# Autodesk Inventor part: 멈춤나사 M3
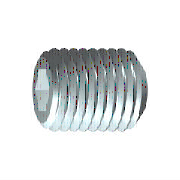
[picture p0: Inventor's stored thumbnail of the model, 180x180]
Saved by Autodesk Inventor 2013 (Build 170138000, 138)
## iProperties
IsCustomPart: 1
Created: 2012-02
Part Number: 멈춤나사 M3
Material: 강철, 연강
Description: 6각 소켓 머리 없는 멈춤 나사
Document SubType Name: Modeling
Standard: KS B 1028
Designer: mduedu
Standards Organization: KS
Language: ko-KR
Size Designation: 납작점M3x8
Categories: <MemberInstance><Categories><Category DisplayName="조임쇠" InternalName="e4da775c-781d-43d5-af7c-5136215cf5a6" Mnemonic="FSTN"><Category DisplayName="볼트" InternalN
Density: 1 g/cm^3
Author: mduedu
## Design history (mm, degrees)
sketch "스케치1"
  geometry: L1 (0, 0)-(5.5, 0); L2 (8, 0.866)-(8, 1.5); L3 (8, 1.5)-(0, 1.5); L4 (8, 0.866)-(6, 0.866); L5 (6, 0.866)-(5.5, 0); L6 (0, -0.3)-(0, 1.8) reference; L7 (0, 1.5)-(0, 0)
  constraints: 13 end point, 3 parallel, 1 collinear, 1 perpendicular, 1 point on line
  dimensions: "d0" = 2 distance of L2.start L4.end (= INTI); "d1" = 60 deg angle of L5 L1; "d2" = 3 diameter of L3 L1 (= NND); "d3" = 1.73205 diameter of L4 L1 (= 1.1547 x SW); "d5" = 8 distance from line of L2 L3.end (= NLG)
revolve "본체" sketch "스케치1" stored, may be unused: angle "d6" = 90 deg
sketch "스케치2"
  geometry: L1 (-0.433, 0.75)-(0.433, 0.75); L2 (0.433, 0.75)-(0.866, 0); L3 (0.866, 0)-(0.433, -0.75); L4 (0.433, -0.75)-(-0.433, -0.75); L5 (-0.433, -0.75)-(-0.866, 0); L6 (-0.866, 0)-(-0.433, 0.75); A1 r 0.866 centre (0, 0) between (-0.433, 0.75) and (0.433, 0.75) reference; 2 further points
  constraints: 12 end point, 2 point on circle, 1 coincident, 1 horizontal, 11 other
extrude "슬롯" join sketch "스케치2" taper "d9" = 0 deg; stored distance "d21" = 10
workaxis "Work Axis1"
workplane "Work Plane1"
body "Solid1"
chamfer "모따기1" distance "d7" = 0.30673 (= -0.5 x GD1 + 0.5 x NND); stored, may be unused: angle "d8" = 45 deg (= FAWI), second distance "d29" = 0.30673 (= -0.5 x GD1 + 0.5 x NND)
feature "스레드" dims "d11" = 8 (= NLG), "d12" = 0
chamfer "모따기2" distance "d13" = 0.30673 (= -0.5 x GD1 + 0.5 x NND); stored, may be unused: angle "d14" = 45 deg (= FAWI), second distance "d30" = 0.30673 (= -0.5 x GD1 + 0.5 x NND)
other parameters: "NND" = 3 [user parameter; used in 5 equation terms], "NLG" = 8 [user parameter; used in 2 equation terms], "INTI" = 2 [user parameter; used in 1 equation term], "FAWI" = 45 deg [user parameter; used in 2 equation terms], "SW" = 1.5 [user parameter; used in 2 equation terms], "GD1" = 2.38655 (= THREADDIA - 1.2269 x PTC) [user parameter; used in 4 equation terms], "d4" = 0, "FAWI1" = 45 deg [user parameter], "d15" = 0, "d31" = 0, "GUL" = 0.30673 (= 0.61345 x PTC) [user parameter], "SPD" = 2 [user parameter], "TOA" = 30 deg [user parameter], "THREADDIA" = 3 [user parameter; used in 1 equation term], "PTC" = 0.5 [user parameter; used in 4 equation terms], "GAL" = 0.30673 (= 0.61345 x PTC) [user parameter], "E0" = 1.7325 (= 1.155 x SW) [user parameter]
